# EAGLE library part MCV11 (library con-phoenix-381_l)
Mini-Combicon 3.81mm vertikal 11polig (ohne Gegenstecker)
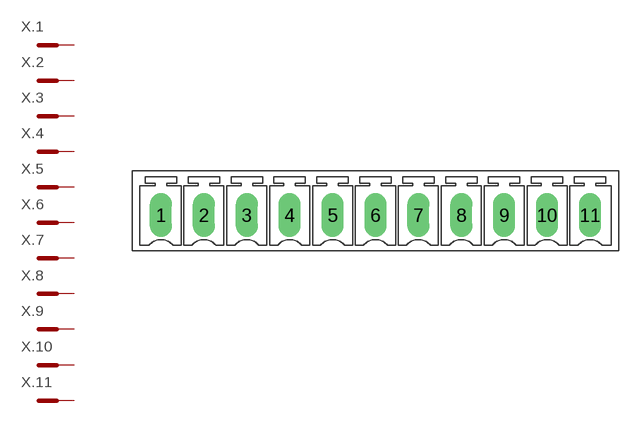
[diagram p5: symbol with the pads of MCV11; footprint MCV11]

Designator prefix X; gates .1=MCST .2=MCST .3=MCST .4=MCST .5=MCST .6=MCST .7=MCST .8=MCST .9=MCST .10=MCST .11=MCST

## MCV11  [MCV11]
1  .1:SK  pas
2  .2:SK  pas
3  .3:SK  pas
4  .4:SK  pas
5  .5:SK  pas
6  .6:SK  pas
7  .7:SK  pas
8  .8:SK  pas
9  .9:SK  pas
10  .10:SK  pas
11  .11:SK  pas

## Footprint MCV11 (pad centres in mm)
Mini-Combicon 3.81mm vertikal 11-polig (ohne Gegenstecker)
drill 1.3 pad 1.905 long: 1 -19.05,0; 2 -15.24,0; 3 -11.43,0; 4 -7.62,0; 5 -3.81,0; 6 0,0; 7 3.81,0; 8 7.62,0; 9 11.43,0; 10 15.24,0; 11 19.05,0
